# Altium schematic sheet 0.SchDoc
size A4
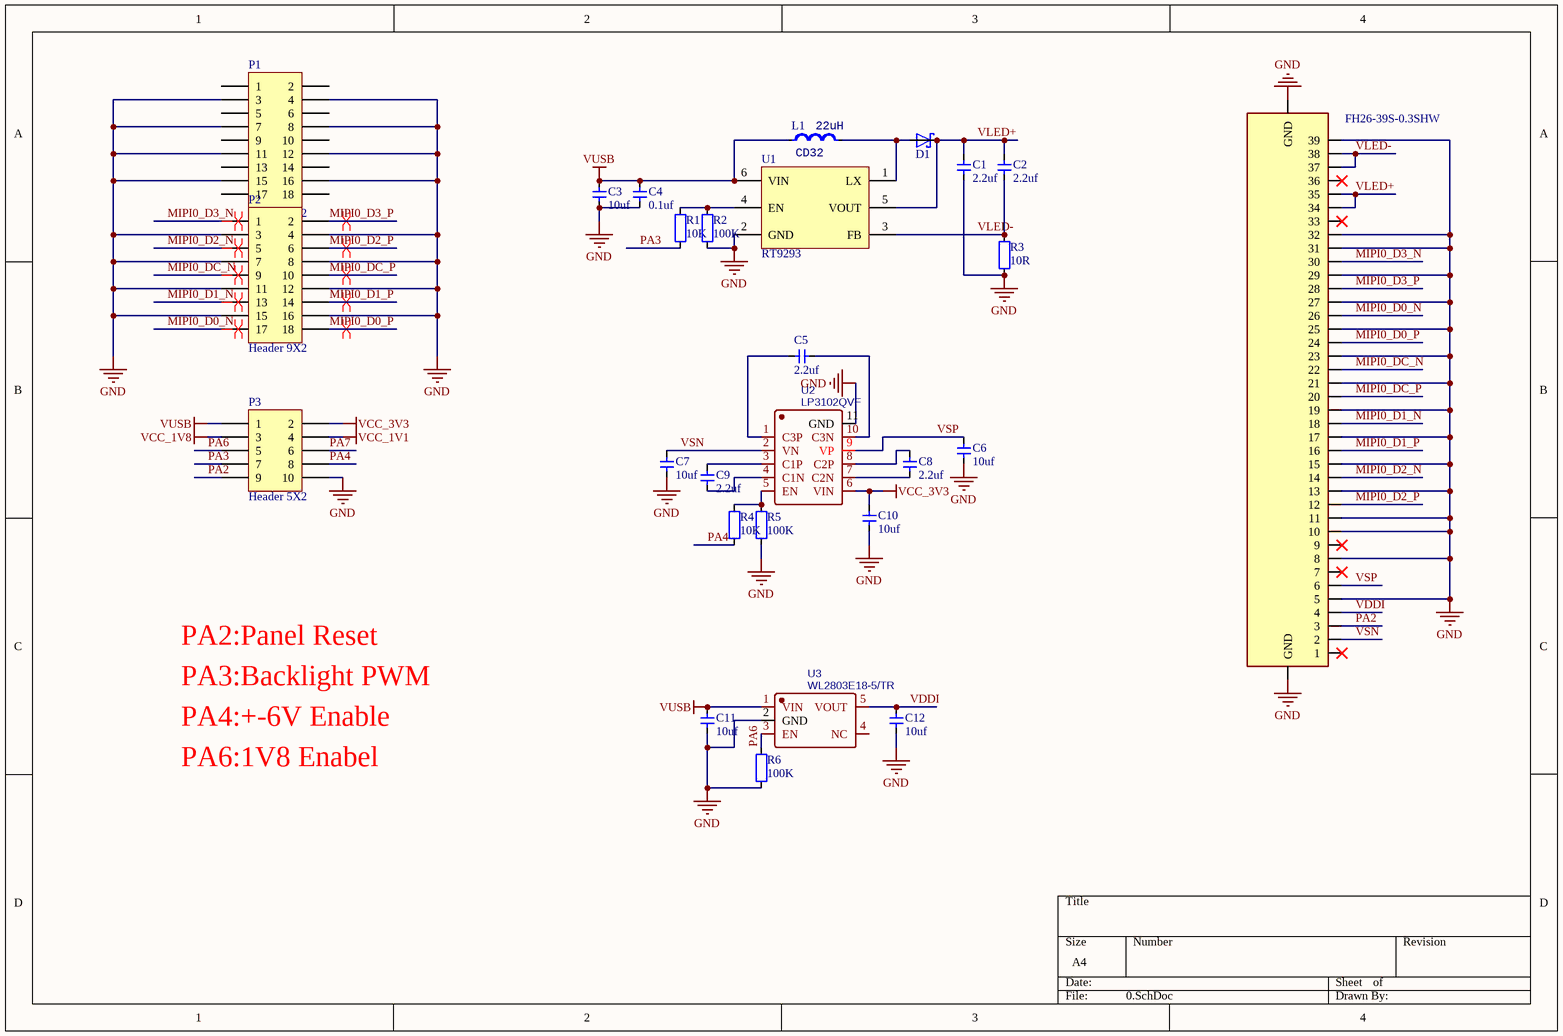
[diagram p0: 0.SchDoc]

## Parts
1  FH26-39S-0.3SHW  [FH26-39S-0.3SHW]
C1  2.2uf  [0603_CAP]
C2  2.2uf  [0603_CAP]
C3  10uf  [0603_CAP]
C4  0.1uf  [0603_CAP]
C5  2.2uf  [0603_CAP]
C6  10uf  [0603_CAP]
C7  10uf  [0603_CAP]
C8  2.2uf  [0603_CAP]
C9  2.2uf  [0603_CAP]
C10  10uf  [0603_CAP]
C11  10uf  [0603_CAP]
C12  10uf  [0603_CAP]
D1  RSX501L-20  [SOD-123F_L2.8-W1.8-LS3.7-RD]  (value not drawn)
L1  value 22uH  [IND_CD32]  (hidden comment: CD32)
P1  Header 9X2  [HDR2X9]
P2  Header 9X2  [HDR2X9]
P3  Header 5X2  [HDR2X5]
R1  10K  [0603_RES]
R2  100K  [0603_RES]
R3  10R  [0603_RES]
R4  10K  [0603_RES]
R5  100K  [0603_RES]
R6  100K  [0603_RES]
U1  RT9293  [SOT23-6]
U2  LP3102QVF  [TDFN-10_L3.0-W3.0-P0.50-BL-EP]
U3  WL2803E18-5/TR  [SOT-23-5_L3.0-W1.7-P0.95-LS2.8-TL]

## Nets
GND: 1.5 1.8 1.10 1.11 1.13 1.15 1.17 1.19 1.21 1.23 1.25 1.27 1.29 1.31 1.32 1.39 1.GND1(GND) 1.GND2(GND) C1.1 C3.1 C4.1 C6.1 C7.1 C10.1 C11.1 C12.1 P1.3 P1.4 P1.7 P1.8 P1.11 P1.12 P1.15 P1.16 P2.3 P2.4 P2.7 P2.8 P2.11 P2.12 P2.15 P2.16 P3.10 R2.2 R3.2 R5.2 R6.2 U1.2(GND) U2.11(GND) U3.2(GND)
VCC_1V1: P3.4
VCC_1V8: P3.3
VCC_3V3: C10.2 P3.2 U2.6(VIN)
VUSB: C3.2 C4.2 C11.2 L1.1 P3.1 U1.6(VIN) U3.1(VIN)
MIPI0_D0_N: 1.26 P2.17
MIPI0_D0_P: 1.24 P2.18
MIPI0_D1_N: 1.18 P2.13
MIPI0_D1_P: 1.16 P2.14
MIPI0_D2_N: 1.14 P2.5
MIPI0_D2_P: 1.12 P2.6
MIPI0_D3_N: 1.30 P2.1
MIPI0_D3_P: 1.28 P2.2
MIPI0_DC_N: 1.22 P2.9
MIPI0_DC_P: 1.20 P2.10
PA2: 1.3 P3.9
PA3: P3.7 R1.2
PA4: P3.8 R4.2
PA6: P3.5 R6.1 U3.3(EN)
PA7: P3.6
VDDI: 1.4 C12.2 U3.5(VOUT)
VLED+: 1.34 1.35 C1.2 C2.2 D1.1 U1.5(VOUT)
VLED-: 1.37 1.38 C2.1 R3.1 U1.3(FB)
VSN: 1.2 C7.2 U2.2(VN)
VSP: 1.6 C6.2 U2.9(VP)
NetC5_1: C5.1 U2.10(C3N)
NetC5_2: C5.2 U2.1(C3P)
NetC8_1: C8.1 U2.8(C2P)
NetC8_2: C8.2 U2.7(C2N)
NetC9_1: C9.1 U2.3(C1P)
NetC9_2: C9.2 U2.4(C1N)
NetD1_2: D1.2 L1.2 U1.1(LX)
NetR1_1: R1.1 R2.1 U1.4(EN)
NetR4_1: R4.1 R5.1 U2.5(EN)

Not connected (* = marked no-connect by the designer): 1 1* 7* 9* 33* 36*; P1 1 2 5 6 9 10 13 14 17 18; U3 4(NC)

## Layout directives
differential pair: MIPI0_D0_N, MIPI0_D0_P, MIPI0_D1_N, MIPI0_D1_P, MIPI0_D2_N, MIPI0_D2_P, MIPI0_D3_N, MIPI0_D3_P, MIPI0_DC_N, MIPI0_DC_P

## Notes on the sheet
- PA2:Panel Reset
- PA3:Backlight PWM
- PA4:+-6V Enable
- PA6:1V8 Enabel

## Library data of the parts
1 = FH26-39S-0.3SHW: 39 Position FPC Connector Contacts, Bottom 0.012 _0.30mm_ Surface Mount, Right Angle; MF: Hirose
C1-C12 = 电容-0402: Capacitor; Value: 0.1u
D1 = RSX501L-20: Diode Schottky 40V 1A Surface Mount SMA _DO-214AC_; MP: SS14; MF: ON Semiconductor
L1 = Ind_CD32: Inductor; Specification: ±5% 100mA
P1 P2 = Header 9X2: Header, 9-Pin, Dual row
P3 = Header 5X2: Header, 5-Pin, Dual row
R1-R6 = 电阻-0402: Resistor; Value: 22R
U1 = RT9293: LCD-LED Driver
U2 = LP3102QVF: BOM_Manufacturer: LOWPOWER; Contributor: LCSC; SMT Type: Extend
U3 = WL2803E18-5/TR: BOM_Manufacturer: WILLSEMI(Will Semicon); Contributor: LCSC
